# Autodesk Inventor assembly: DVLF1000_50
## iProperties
Created: 2010-03
Part Number: DVLF1000_50
Document SubType Name: Assembly
Designer: TB
Mass: 3335.55 g
Surface Area: 3607.59 cm^2
Volume: 3335.55 cm^3
Density: 1 g/cm^3
Description: KM DVLF 100/50 - 100 mm
Slaglengde: 100.000 mm
Author: TB
